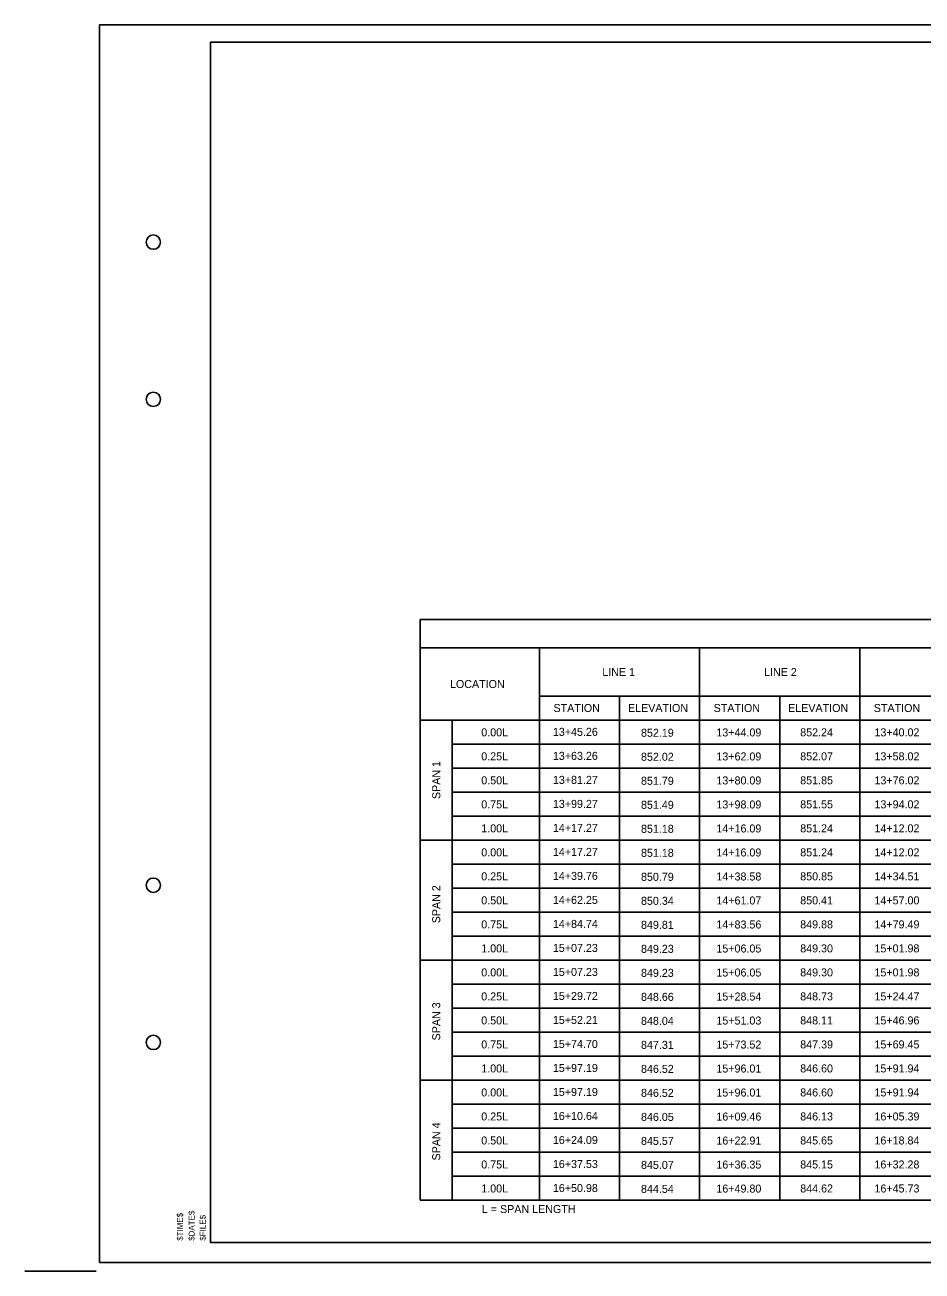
# Model space of a CAD drawing. Extents: x 1466871.1 to 1466907, y 570850.5 to 570872.5.
# Drawn here: x 1466871.07 to 1466886.76, y 570850.46 to 570872.26 of the extents above; entities that cross this region are included whole.
import ezdxf

# ---------------------------------------------------------------- set-up
doc = ezdxf.new("R2010")
doc.units = 0
for name, color, linetype in [('BR_P_Gen_Text', 7, 'Continuous'), ('Default', 7, 'Continuous'), ('SH_Border', 7, 'Continuous'), ('SH_Cut_Line', 7, 'Continuous')]:
    doc.layers.add(name, color=color, linetype=linetype)

msp = doc.modelspace()

# ---------------------------------------------------------------- linework, layer by layer
at = {"layer": 'Default'}
for p, q in [((1466877.978, 570861.863), (1466877.978, 570851.704)), ((1466877.978, 570861.863), (1466899.667, 570861.863)), ((1466877.978, 570861.364), (1466899.667, 570861.364)), ((1466880.067, 570861.364), (1466880.067, 570851.704)), ((1466882.867, 570861.364), (1466882.867, 570851.704)), ((1466885.667, 570861.364), (1466885.667, 570851.704)), ((1466880.067, 570860.524), (1466899.667, 570860.524)), ((1466881.467, 570860.524), (1466881.467, 570851.704)), ((1466884.267, 570860.524), (1466884.267, 570851.704)), ((1466877.978, 570860.104), (1466899.667, 570860.104)), ((1466878.538, 570860.104), (1466878.538, 570851.704)), ((1466878.538, 570859.684), (1466899.667, 570859.684)), ((1466878.538, 570859.264), (1466899.667, 570859.264)), ((1466878.538, 570858.844), (1466899.667, 570858.844)), ((1466878.538, 570858.424), (1466899.667, 570858.424)), ((1466877.978, 570858.004), (1466899.667, 570858.004)), ((1466878.538, 570857.584), (1466899.667, 570857.584)), ((1466878.538, 570857.164), (1466899.667, 570857.164)), ((1466878.538, 570856.744), (1466899.667, 570856.744)), ((1466878.538, 570856.324), (1466899.667, 570856.324)), ((1466877.978, 570855.904), (1466899.667, 570855.904)), ((1466878.538, 570855.484), (1466899.667, 570855.484)), ((1466878.538, 570855.484), (1466899.667, 570855.484)), ((1466878.538, 570855.064), (1466899.667, 570855.064)), ((1466878.538, 570855.064), (1466899.667, 570855.064)), ((1466878.538, 570854.644), (1466899.667, 570854.644)), ((1466878.538, 570854.644), (1466899.667, 570854.644)), ((1466878.538, 570854.224), (1466899.667, 570854.224)), ((1466877.978, 570853.804), (1466899.667, 570853.804)), ((1466877.978, 570853.804), (1466899.667, 570853.804)), ((1466878.538, 570853.384), (1466899.667, 570853.384)), ((1466878.538, 570853.384), (1466899.667, 570853.384)), ((1466878.538, 570852.964), (1466899.667, 570852.964)), ((1466878.538, 570852.964), (1466899.667, 570852.964)), ((1466878.538, 570852.544), (1466899.667, 570852.544)), ((1466878.538, 570852.544), (1466899.667, 570852.544)), ((1466878.538, 570852.124), (1466899.667, 570852.124)), ((1466877.978, 570851.704), (1466899.667, 570851.704))]:
    msp.add_line(p, q, dxfattribs=at)
at = {"layer": 'SH_Border'}
msp.add_lwpolyline([(1466874.314, 570871.964), (1466905.814, 570871.964), (1466905.814, 570850.964), (1466874.314, 570850.964)], close=True, dxfattribs=at)
for centre in [(1466873.314, 570868.464), (1466873.314, 570865.714), (1466873.314, 570857.214), (1466873.314, 570854.464)]:
    msp.add_circle(centre, 0.125, dxfattribs=at)
at = {"layer": 'SH_Cut_Line'}
msp.add_line((1466872.314, 570850.464), (1466871.07, 570850.464), dxfattribs=at)
msp.add_lwpolyline([(1466906.376, 570850.614), (1466872.376, 570850.614), (1466872.376, 570872.264), (1466906.376, 570872.264)], close=True, dxfattribs=at)

# ---------------------------------------------------------------- texts
at = {"layer": 'BR_P_Gen_Text'}
for s, p in [('LINE 1', (1466881.165, 570860.874)), ('LINE 2', (1466883.994, 570860.874)), ('LOCATION', (1466878.502, 570860.664)), ('STATION', (1466880.312, 570860.244)), ('ELEVATION', (1466881.614, 570860.244)), ('STATION', (1466883.112, 570860.244)), ('ELEVATION', (1466884.414, 570860.244)), ('STATION', (1466885.912, 570860.244)), ('0.00L', (1466879.049, 570859.819)), ('13+45.26', (1466880.301, 570859.827)), ('852.19', (1466881.842, 570859.811)), ('13+44.09', (1466883.16, 570859.817)), ('852.24', (1466884.626, 570859.819)), ('13+40.02', (1466885.924, 570859.819)), ('0.25L', (1466879.049, 570859.399)), ('13+63.26', (1466880.301, 570859.407)), ('852.02', (1466881.842, 570859.391)), ('13+62.09', (1466883.16, 570859.397)), ('852.07', (1466884.626, 570859.399)), ('13+58.02', (1466885.924, 570859.399)), ('0.50L', (1466879.049, 570858.979)), ('13+81.27', (1466880.301, 570858.987)), ('851.79', (1466881.842, 570858.971)), ('13+80.09', (1466883.16, 570858.977)), ('851.85', (1466884.626, 570858.979)), ('13+76.02', (1466885.924, 570858.979)), ('0.75L', (1466879.049, 570858.559)), ('13+99.27', (1466880.301, 570858.567)), ('851.49', (1466881.842, 570858.551)), ('13+98.09', (1466883.16, 570858.557)), ('851.55', (1466884.626, 570858.559)), ('13+94.02', (1466885.924, 570858.559)), ('14+17.27', (1466880.301, 570858.147)), ('1.00L', (1466879.049, 570858.139)), ('851.18', (1466881.842, 570858.131)), ('14+16.09', (1466883.16, 570858.137)), ('851.24', (1466884.626, 570858.139)), ('14+12.02', (1466885.924, 570858.139)), ('0.00L', (1466879.049, 570857.719)), ('14+17.27', (1466880.301, 570857.727)), ('851.18', (1466881.842, 570857.711)), ('14+16.09', (1466883.16, 570857.717)), ('851.24', (1466884.626, 570857.719)), ('14+12.02', (1466885.924, 570857.719)), ('0.25L', (1466879.049, 570857.299)), ('14+39.76', (1466880.301, 570857.307)), ('850.79', (1466881.842, 570857.291)), ('14+38.58', (1466883.16, 570857.297)), ('850.85', (1466884.626, 570857.299)), ('14+34.51', (1466885.924, 570857.299)), ('0.50L', (1466879.049, 570856.879)), ('14+62.25', (1466880.301, 570856.887)), ('850.34', (1466881.842, 570856.871)), ('14+61.07', (1466883.16, 570856.877)), ('850.41', (1466884.626, 570856.879)), ('14+57.00', (1466885.924, 570856.879)), ('0.75L', (1466879.049, 570856.459)), ('14+84.74', (1466880.301, 570856.467)), ('849.81', (1466881.842, 570856.451)), ('14+83.56', (1466883.16, 570856.457)), ('849.88', (1466884.626, 570856.459)), ('14+79.49', (1466885.924, 570856.459)), ('1.00L', (1466879.049, 570856.039)), ('15+07.23', (1466880.301, 570856.047)), ('849.23', (1466881.842, 570856.031)), ('15+06.05', (1466883.16, 570856.037)), ('849.30', (1466884.626, 570856.039)), ('15+01.98', (1466885.924, 570856.039)), ('0.00L', (1466879.049, 570855.619)), ('15+07.23', (1466880.301, 570855.627)), ('849.23', (1466881.842, 570855.611)), ('15+06.05', (1466883.16, 570855.617)), ('849.30', (1466884.626, 570855.619)), ('15+01.98', (1466885.924, 570855.619)), ('0.25L', (1466879.049, 570855.199)), ('15+29.72', (1466880.301, 570855.207)), ('848.66', (1466881.842, 570855.191)), ('15+28.54', (1466883.16, 570855.197)), ('848.73', (1466884.626, 570855.199)), ('15+24.47', (1466885.924, 570855.199)), ('0.50L', (1466879.049, 570854.779)), ('15+52.21', (1466880.301, 570854.787)), ('848.04', (1466881.842, 570854.771)), ('15+51.03', (1466883.16, 570854.777)), ('848.11', (1466884.626, 570854.779)), ('15+46.96', (1466885.924, 570854.779)), ('0.75L', (1466879.049, 570854.359)), ('15+74.70', (1466880.301, 570854.367)), ('847.31', (1466881.842, 570854.351)), ('15+73.52', (1466883.16, 570854.357)), ('847.39', (1466884.626, 570854.359)), ('15+69.45', (1466885.924, 570854.359)), ('1.00L', (1466879.049, 570853.939)), ('15+97.19', (1466880.301, 570853.947)), ('846.52', (1466881.842, 570853.931)), ('15+96.01', (1466883.16, 570853.937)), ('846.60', (1466884.626, 570853.939)), ('15+91.94', (1466885.924, 570853.939)), ('0.00L', (1466879.049, 570853.519)), ('15+97.19', (1466880.301, 570853.527)), ('846.52', (1466881.842, 570853.511)), ('15+96.01', (1466883.16, 570853.517)), ('846.60', (1466884.626, 570853.519)), ('15+91.94', (1466885.924, 570853.519)), ('0.25L', (1466879.049, 570853.099)), ('16+10.64', (1466880.301, 570853.107)), ('846.05', (1466881.842, 570853.091)), ('16+09.46', (1466883.16, 570853.097)), ('846.13', (1466884.626, 570853.099)), ('16+05.39', (1466885.924, 570853.099)), ('0.50L', (1466879.049, 570852.679)), ('16+24.09', (1466880.301, 570852.687)), ('845.57', (1466881.842, 570852.671)), ('16+22.91', (1466883.16, 570852.677)), ('845.65', (1466884.626, 570852.679)), ('16+18.84', (1466885.924, 570852.679)), ('16+37.53', (1466880.301, 570852.267)), ('0.75L', (1466879.049, 570852.259)), ('845.07', (1466881.842, 570852.251)), ('16+36.35', (1466883.16, 570852.257)), ('845.15', (1466884.626, 570852.259)), ('16+32.28', (1466885.924, 570852.259)), ('1.00L', (1466879.049, 570851.839)), ('16+50.98', (1466880.301, 570851.847)), ('844.54', (1466881.842, 570851.831)), ('16+49.80', (1466883.16, 570851.837)), ('844.62', (1466884.626, 570851.839)), ('16+45.73', (1466885.924, 570851.839)), ('L = SPAN LENGTH', (1466879.059, 570851.479))]:
    msp.add_text(s, height=0.14, dxfattribs=at).set_placement(p)
for s, height, rotation, p in [('SPAN 1', 0.14, 90, (1466878.332, 570858.721)), ('SPAN 2', 0.14, 90, (1466878.331, 570856.548)), ('SPAN 3', 0.14, 90, (1466878.331, 570854.499)), ('SPAN 4', 0.14, 90, (1466878.331, 570852.399)), ('$TIME$', 0.1043, 90.0067, (1466873.832, 570850.994)), ('$DATE$', 0.1043, 90.0067, (1466874.036, 570850.994)), ('$FILE$', 0.1043, 90.0067, (1466874.231, 570850.995))]:
    msp.add_text(s, height=height, rotation=rotation, dxfattribs=at).set_placement(p)

doc.saveas('drawing.dxf')
